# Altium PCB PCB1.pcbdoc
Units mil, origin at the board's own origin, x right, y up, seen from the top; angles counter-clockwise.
Board outline 3640 x 4230 mil, 2 copper layers (Top Layer, Bottom Layer); 68 components, 95 nets, 332 pads, 42 vias.
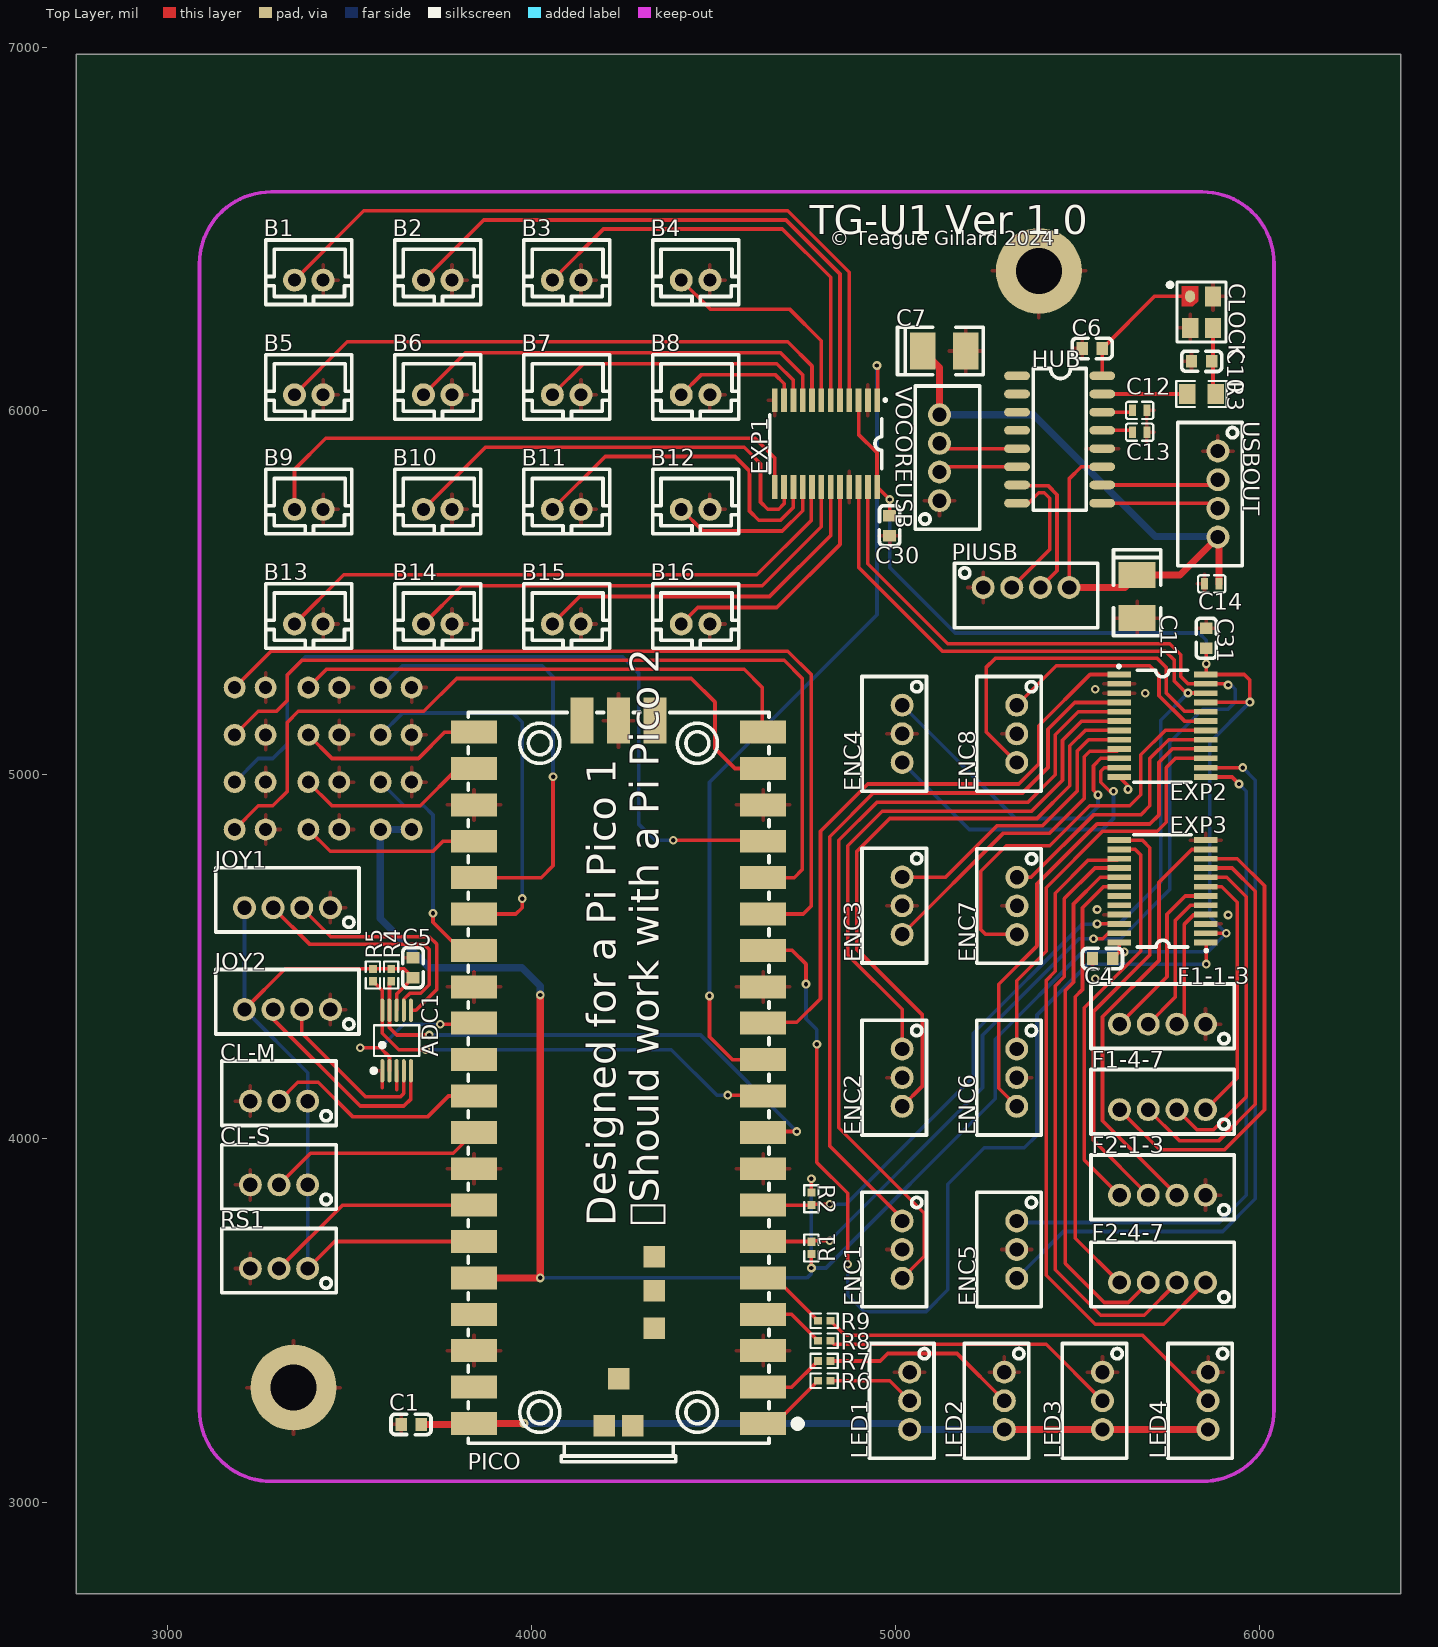
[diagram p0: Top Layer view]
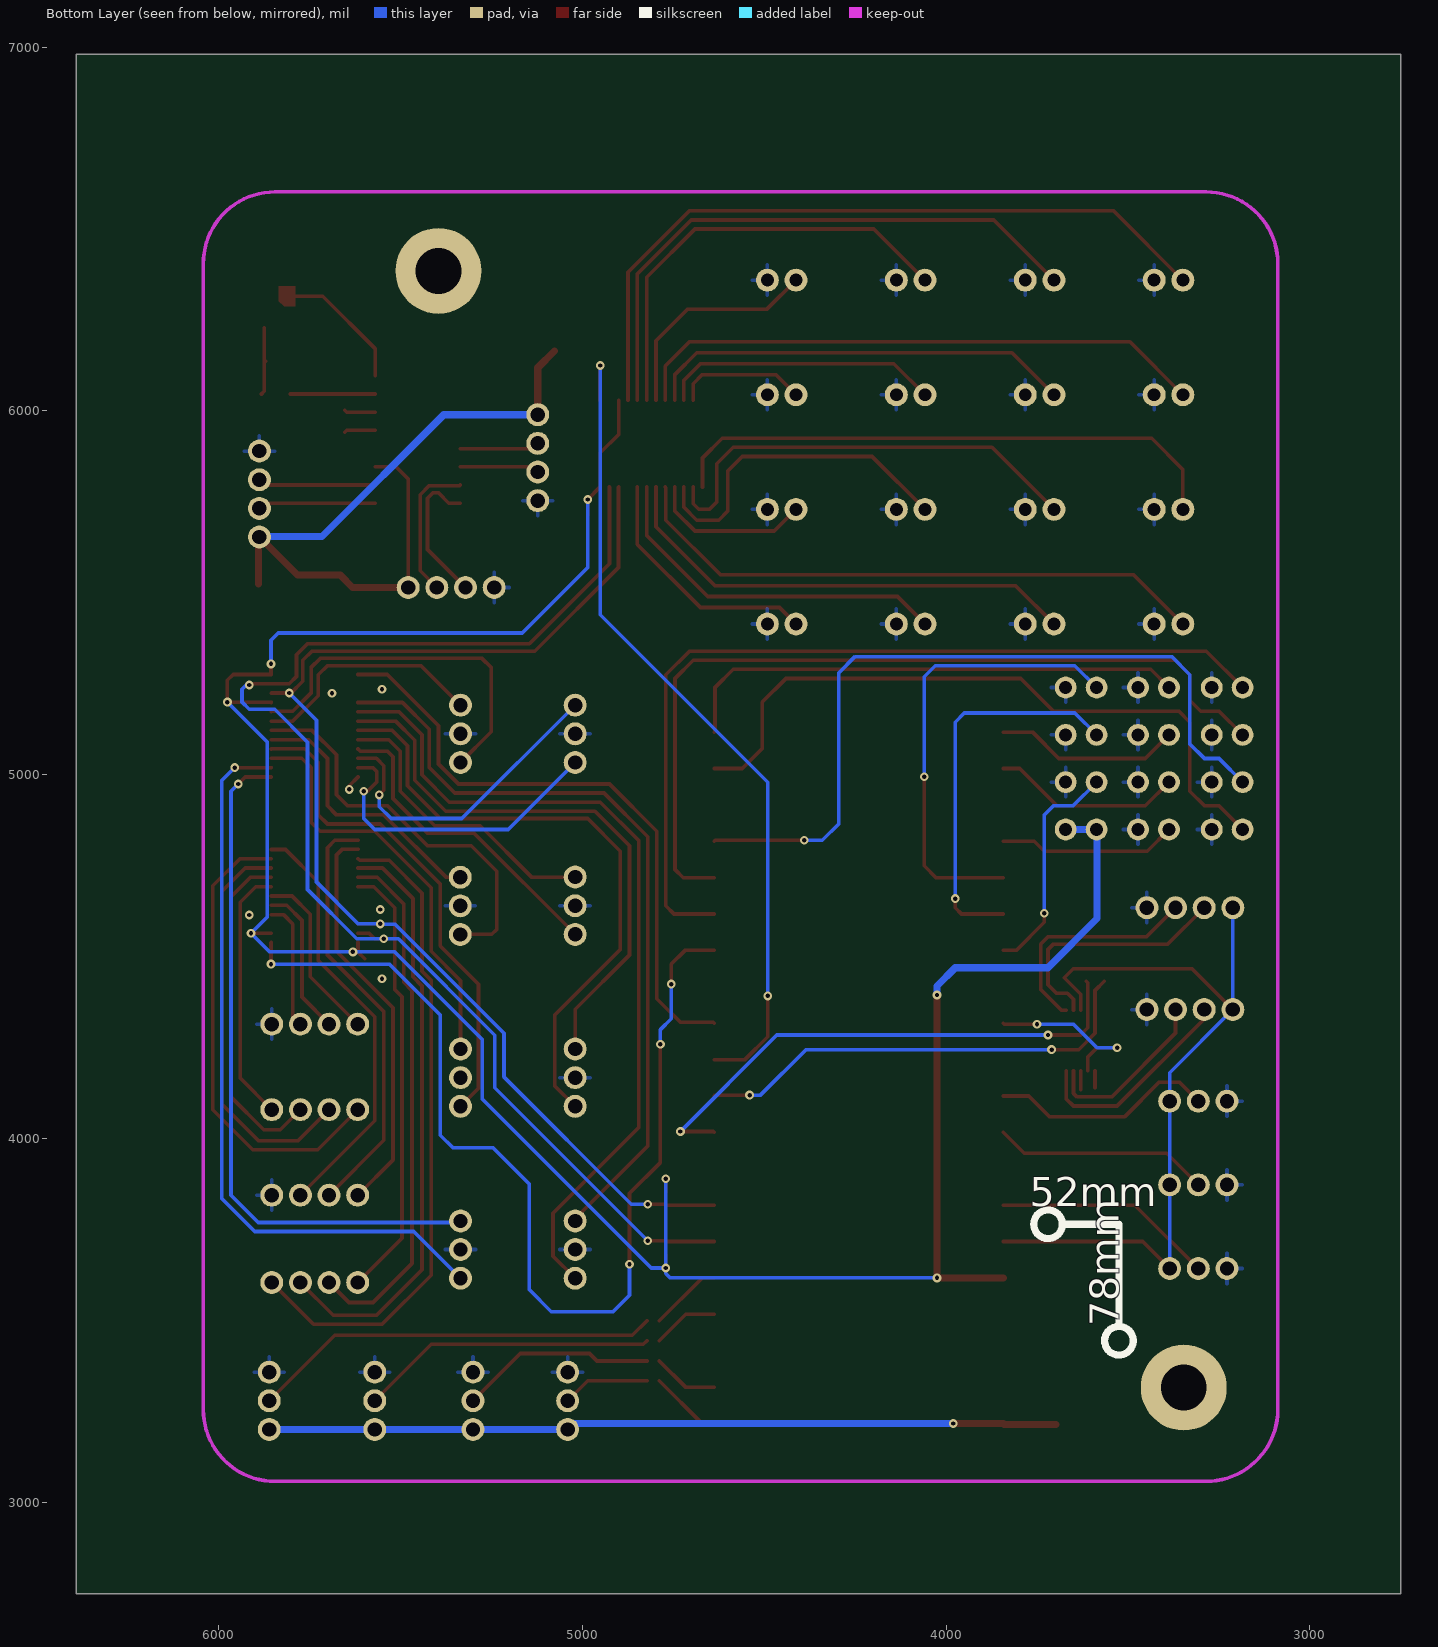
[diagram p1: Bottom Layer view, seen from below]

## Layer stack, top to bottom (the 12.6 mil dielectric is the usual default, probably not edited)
Top Layer: signal copper (thickness not stored)
Dielectric: dielectric 12.6, FR-4, Dk 4.8
Bottom Layer: signal copper (thickness not stored)

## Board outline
6390,2750 2750,2750 2750,6980 6390,6980

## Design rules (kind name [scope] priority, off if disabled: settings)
Clearance copperThickness1oz [All] p1: gap=7 ignorepadtopadclearanceinfootprint=FALSE except(4: Track-Track; 6: Track-SMDPad SMDPad-SMDPad Track-THPad SMDPad-THPad THPad-THPad Track-Via SMDPad-Via THPad-Via Via-Via SMDPad-Fill THPad-Fill Via-Fill Fill-Fill Track-Region SMDPad-Region THPad-Region Via-Region Region-Region Track-Poly SMDPad-Poly THPad-Poly Via-Poly Fill-Poly Region-Poly Poly-Poly Track-Text SMDPad-Text THPad-Text Via-Text Fill-Text Region-Text Poly-Text Text-Text; 6.9: Track-Hole SMDPad-Hole THPad-Hole Via-Hole Fill-Hole Region-Hole Poly-Hole Text-Hole Sheet-Hole; 11.8: Track-Fill Fill-Region Track-Sheet SMDPad-Sheet THPad-Sheet Via-Sheet Fill-Sheet Region-Sheet Poly-Sheet Text-Sheet)
Clearance copperThickness2oz [All] p1: gap=7 ignorepadtopadclearanceinfootprint=FALSE except(6: Track-SMDPad SMDPad-SMDPad Track-THPad SMDPad-THPad THPad-THPad Track-Via SMDPad-Via THPad-Via Via-Via SMDPad-Fill THPad-Fill Via-Fill Fill-Fill Track-Region SMDPad-Region THPad-Region Via-Region Region-Region Track-Poly SMDPad-Poly THPad-Poly Via-Poly Fill-Poly Region-Poly Poly-Poly Track-Text SMDPad-Text THPad-Text Via-Text Fill-Text Region-Text Poly-Text Text-Text; 6.9: Track-Hole SMDPad-Hole THPad-Hole Via-Hole Fill-Hole Region-Hole Poly-Hole Text-Hole Sheet-Hole; 8: Track-Track; 11.8: Track-Fill Fill-Region Track-Sheet SMDPad-Sheet THPad-Sheet Via-Sheet Fill-Sheet Region-Sheet Poly-Sheet Text-Sheet)
DiffPairsRouting differentialPair [All] p1: maxuncoupledlength=10 maxlimit=6 mostfreqgap=6 toplayer_minwidth=5 toplayer_prefwidth=10 toplayer_maxwidth=100 bottomlayer_minwidth=5 bottomlayer_prefwidth=10 bottomlayer_maxwidth=100
PasteMaskExpansion pasteMaskExpansion [All] p1:
PlaneConnect innerPlane [All] p1: planeconnectstyle=Relief reliefexpansion=20 reliefentries=4 reliefconductorwidth=10 reliefairgap=10
PolygonConnect copperRegion [All] p1: connectstyle=Relief reliefentries=4 reliefconductorwidth=10 polygonreliefangle="90 Angle" airgapwidth=10
RoutingVias viaSize [All] p1: viastyle="Through Hole" holewidth=12.0078 minholewidth=11.811 maxholewidth=248.0314 width=24.0158 minwidth=19.685 maxwidth=393.7008
SolderMaskExpansion solderMaskExpansion [All] p1: useseparateexpansions=TRUE expansion=2 expansionbottom=2
Width copperThickness1oz [All] p1: maxlimit=100 minlimit=5 preferedwidth=10
Width copperThickness2oz [All] p1: maxlimit=100 minlimit=8 preferedwidth=10

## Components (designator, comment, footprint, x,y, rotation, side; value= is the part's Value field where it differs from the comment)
ADC1 "ADS1115IDGSR" MSOP-10_L3.0-W3.0-P0.50-LS5.0-BL 3630,4270 r0 top
B1 "B2B-PH-K-S(LF)(SN)" CONN-TH_B2B-PH-K-S 3388.7,6359.53 r0 top
B2 "B2B-PH-K-S(LF)(SN)" CONN-TH_B2B-PH-K-S 3743.03,6359.53 r0 top
B3 "B2B-PH-K-S(LF)(SN)" CONN-TH_B2B-PH-K-S 4097.36,6359.53 r0 top
B4 "B2B-PH-K-S(LF)(SN)" CONN-TH_B2B-PH-K-S 4451.69,6359.53 r0 top
B5 "B2B-PH-K-S(LF)(SN)" CONN-TH_B2B-PH-K-S 3388.7,6044.57 r0 top
B6 "B2B-PH-K-S(LF)(SN)" CONN-TH_B2B-PH-K-S 3743.03,6044.57 r0 top
B7 "B2B-PH-K-S(LF)(SN)" CONN-TH_B2B-PH-K-S 4097.36,6044.57 r0 top
B8 "B2B-PH-K-S(LF)(SN)" CONN-TH_B2B-PH-K-S 4451.69,6044.57 r0 top
B9 "B2B-PH-K-S(LF)(SN)" CONN-TH_B2B-PH-K-S 3388.7,5729.61 r0 top
B10 "B2B-PH-K-S(LF)(SN)" CONN-TH_B2B-PH-K-S 3743.03,5729.61 r0 top
B11 "B2B-PH-K-S(LF)(SN)" CONN-TH_B2B-PH-K-S 4097.36,5729.61 r0 top
B12 "B2B-PH-K-S(LF)(SN)" CONN-TH_B2B-PH-K-S 4451.69,5729.61 r0 top
B13 "B2B-PH-K-S(LF)(SN)" CONN-TH_B2B-PH-K-S 3388.7,5414.65 r0 top
B14 "B2B-PH-K-S(LF)(SN)" CONN-TH_B2B-PH-K-S 3743.03,5414.65 r0 top
B15 "B2B-PH-K-S(LF)(SN)" CONN-TH_B2B-PH-K-S 4097.36,5414.65 r0 top
B16 "B2B-PH-K-S(LF)(SN)" CONN-TH_B2B-PH-K-S 4451.69,5414.65 r0 top
C1 "100n" C0603 3670,3215 r0 top
C4 "100nF" C0603 5570,4495 r0 top
C5 "100nF" C0603 3675,4470 r270 top
C6 "30pF" C0603 5542.03,6171.68 r0 top
C7 "100uF" CAP-SMD_L3.5-W2.8 5135,6165 r0 top
C10 "30pF" C0603 5842.03,6136.68 r180 top
C11 "100uF" CAP-SMD_L3.5-W2.8 5665,5490 r270 top
C12 "10uF" C0402 5672.03,6001.68 r0 top
C13 "10uF" C0402 5672.03,5941.68 r0 top
C14 "10uF" C0402 5870,5525 r180 top
C30 "100nF" C0603 4985,5685 r90 top
C31 "100nF" C0603 5855,5375 r270 top
CL-M "B3B-PH-K-S(LF)(SN)" CONN-TH_B3B-PH-K-S 3306.88,4103.35 r0 top
CL-S "B3B-PH-K-S(LF)(SN)" CONN-TH_B3B-PH-K-S 3306.88,3873.34 r0 top
CLOCK "12MHz" OSC-SMD_4P-L3.2-W2.5-BL 5842.03,6271.68 r270 top
ENC1 "B3B-PH-K-S(LF)(SN)" CONN-TH_B3B-PH-K-S 5019.3,3695.51 r90 top
ENC2 "B3B-PH-K-S(LF)(SN)" CONN-TH_B3B-PH-K-S 5019.3,4167.95 r90 top
ENC3 "B3B-PH-K-S(LF)(SN)" CONN-TH_B3B-PH-K-S 5019.3,4640.4 r90 top
ENC4 "B3B-PH-K-S(LF)(SN)" CONN-TH_B3B-PH-K-S 5019.3,5112.84 r90 top
ENC5 "B3B-PH-K-S(LF)(SN)" CONN-TH_B3B-PH-K-S 5334.26,3695.51 r90 top
ENC6 "B3B-PH-K-S(LF)(SN)" CONN-TH_B3B-PH-K-S 5334.26,4167.95 r90 top
ENC7 "B3B-PH-K-S(LF)(SN)" CONN-TH_B3B-PH-K-S 5335,4640 r90 top
ENC8 "B3B-PH-K-S(LF)(SN)" CONN-TH_B3B-PH-K-S 5334.26,5112.84 r90 top
EXP1 "PCA9555PW,118" TSSOP-24_L7.8-W4.4-P0.65-LS6.4-BL 4810,5910 r180 top
EXP2 "PCA9555PW,118" TSSOP-24_L7.8-W4.4-P0.65-LS6.4-BL 5735,5135 r270 top
EXP3 "PCA9555PW,118" TSSOP-24_L7.8-W4.4-P0.65-LS6.4-BL 5735,4680 r90 top
F1-1-3 "B4B-PH-K-S(LF)(SN)" CONN-TH_B4B-PH-K-S 5735,4315 r0 top
F1-4-7 "B4B-PH-K-S(LF)(SN)" CONN-TH_B4B-PH-K-S 5735,4080 r0 top
F2-1-3 "B4B-PH-K-S(LF)(SN)" CONN-TH_B4B-PH-K-S 5735,3845 r0 top
F2-4-7 "B4B-PH-K-S(LF)(SN)" CONN-TH_B4B-PH-K-S 5735,3605 r0 top
HUB "SL2.1A" SOP-16_L10.0-W3.9-P1.27-LS6.0-BL 5452.03,5921.68 r270 top
JOY1 "B4B-PH-K-S(LF)(SN)" CONN-TH_B4B-PH-K-S 3330,4635 r0 top
JOY2 "B4B-PH-K-S(LF)(SN)" CONN-TH_B4B-PH-K-S 3330,4355 r0 top
LED1 "B3B-PH-K-S(LF)(SN)" CONN-TH_B3B-PH-K-S 5040,3280 r90 top
LED2 "B3B-PH-K-S(LF)(SN)" CONN-TH_B3B-PH-K-S 5300,3280 r90 top
LED3 "B3B-PH-K-S(LF)(SN)" CONN-TH_B3B-PH-K-S 5570,3280 r90 top
LED4 "B3B-PH-K-S(LF)(SN)" CONN-TH_B3B-PH-K-S 5860,3280 r90 top
PICO "PICO" COMM-SMD_L51.0-W21.0-P2.54_SC0916 4240,4180 r90 top
PIUSB "B4B-PH-K-S(LF)(SN)" CONN-TH_B4B-PH-K-S 5360,5515 r180 top
R1 "2.2kΩ" R0402 4770,3700 r90 top
R2 "2.2kΩ" R0402 4770,3835 r270 top
R3 "1kΩ" R0805 5842.03,6046.68 r0 top
R4 "2.2kΩ" R0402 3615,4450 r90 top
R5 "2.2kΩ" R0402 3565,4450 r90 top
R6 "300Ω" R0402 4805,3335 r0 top
R7 "300Ω" R0402 4805,3389.39 r0 top
R8 "300Ω" R0402 4805,3445 r0 top
R9 "300Ω" R0402 4805,3500 r0 top
RS1 "B3B-PH-K-S(LF)(SN)" CONN-TH_B3B-PH-K-S 3306.88,3643.34 r0 top
USBOUT "B4B-PH-K-S(LF)(SN)" CONN-TH_B4B-PH-K-S 5887.03,5771.68 r90 top
VOCOREUSB "B4B-PH-K-S(LF)(SN)" CONN-TH_B4B-PH-K-S 5122.03,5871.68 r270 top

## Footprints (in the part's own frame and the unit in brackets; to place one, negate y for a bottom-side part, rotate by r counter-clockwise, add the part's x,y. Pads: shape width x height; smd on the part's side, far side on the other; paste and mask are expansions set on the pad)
C0402 [mm]
  rect 0.5x0.8 smd: 1(-0.5,0) 2(0.5,0)
  silkscreen extent -0.95,-0.6 0.95,0.6
C0603 [mm]
  rect 0.8x0.9 smd: 1(-0.7,0) 2(0.7,0)
  silkscreen extent -1.41,-0.71 1.39,0.72
CAP-SMD_L3.5-W2.8 [mm]
  rect 1.8x2.6 smd: 1(-1.501,0) 2(1.501,0)
  silkscreen extent -3.26,-1.65 2.73,1.65
COMM-SMD_L51.0-W21.0-P2.54_SC0916 [mm]
  rect 1.6x3.2 smd: 1(-24.445,-10.087) 2(-21.905,-10.087) 3(-19.365,-10.087) 4(-16.825,-10.087) 5(-14.285,-10.087) 6(-11.745,-10.087) 7(-9.205,-10.087) 8(-6.665,-10.087) 9(-4.125,-10.087) 10(-1.585,-10.087) 11(0.955,-10.087) 12(3.495,-10.087) 13(6.035,-10.087) 14(8.575,-10.087) 15(11.115,-10.087) 16(13.655,-10.087) 17(16.195,-10.087) 18(18.735,-10.087) 19(21.275,-10.087) 20(23.815,-10.087) 21(23.815,10.087) 22(21.275,10.087) 23(18.735,10.087) 24(16.195,10.087) 25(13.655,10.087) 26(11.115,10.087) 27(8.575,10.087) 28(6.035,10.087) 29(3.495,10.087) 30(0.955,10.087) 31(-1.585,10.087) 32(-4.125,10.087) 33(-6.665,10.087) 34(-9.205,10.087) 35(-11.745,10.087) 36(-14.285,10.087) 37(-16.825,10.087) 38(-19.365,10.087) 39(-21.905,10.087) 40(-24.445,10.087)
  rect 3.2x1.6 smd: 41(24.615,-2.54) 42(24.615,0) 43(24.615,2.54)
  rect 1.5x1.5 smd: TP1(-21.315,0) TP2(-24.615,1) TP3(-24.615,-1) TP4(-17.815,-2.5) TP5(-15.188,-2.5) TP6(-12.815,-2.5)
  silkscreen extent -27.11,-12.75 25.18,10.5
CONN-TH_B2B-PH-K-S [mm]
  round 1.6 hole 0.9: 1(1,0) 2(-1,0)
  silkscreen extent -3,-1.7 3,2.8
CONN-TH_B3B-PH-K-S [mm]
  round 1.6 hole 1: 1(2,0) 2(0,0) 3(-2,0)
  silkscreen extent -4,-1.7 4,2.8
CONN-TH_B4B-PH-K-S [mm]
  round 1.6 hole 1: 1(3,0) 2(1,0) 3(-1,0) 4(-3,0)
  silkscreen extent -5,-1.7 5,2.8
MSOP-10_L3.0-W3.0-P0.50-LS5.0-BL [mm]
  oval 0.28x1.62 smd: 1(-1,-2.11) 2(-0.5,-2.11) 3(0,-2.11) 4(0.5,-2.11) 5(1,-2.11) 6(1,2.11) 7(0.5,2.11) 8(0,2.11) 9(-0.5,2.11) 10(-1,2.11)
  silkscreen extent -1.74,-2.26 1.58,1.07
OSC-SMD_4P-L3.2-W2.5-BL [mm]
  oval 0.84x0.69 smd: 1(-1.1,-0.8)
  rect 1.4x1.15 smd: 2(1.1,-0.8) 3(1.1,0.8) 4(-1.1,0.8)
  Top Layer region: -1.8,-0.225 -0.762,-0.225 -0.4,-0.604 -0.4,-1.375 -1.8,-1.375
  silkscreen extent -2.1,-2.35 2.1,1.7
R0402 [mm]
  rect 0.566x0.54 smd: 1(-0.433,0) 2(0.433,0)
  silkscreen extent -0.94,-0.5 0.94,0.5
R0805 [mm]
  rect 1.133x1.377 smd: 1(-1,0) 2(1,0)
  silkscreen extent -1.76,-0.92 1.76,0.92
SOP-16_L10.0-W3.9-P1.27-LS6.0-BL [mm]
  oval 0.6x1.8 smd: 1(-4.445,-2.972) 2(-3.175,-2.972) 3(-1.905,-2.972) 4(-0.635,-2.972) 5(0.635,-2.972) 6(1.905,-2.972) 7(3.175,-2.972) 8(4.445,-2.972) 9(4.445,2.972) 10(3.175,2.972) 11(1.905,2.972) 12(0.635,2.972) 13(-0.635,2.972) 14(-1.905,2.972) 15(-3.175,2.972) 16(-4.445,2.972)
  silkscreen extent -4.95,-1.85 4.95,1.85
TSSOP-24_L7.8-W4.4-P0.65-LS6.4-BL [mm]
  rect 0.4x1.65 smd: 1(-3.575,-3.023) 2(-2.925,-3.023) 3(-2.275,-3.023) 4(-1.625,-3.023) 5(-0.975,-3.023) 6(-0.325,-3.023) 7(0.325,-3.023) 8(0.975,-3.023) 9(1.625,-3.023) 10(2.275,-3.023) 11(2.925,-3.023) 12(3.575,-3.023) 13(3.575,3.023) 14(2.925,3.023) 15(2.275,3.023) 16(1.625,3.023) 17(0.975,3.023) 18(0.325,3.023) 19(-0.325,3.023) 20(-0.975,3.023) 21(-1.625,3.023) 22(-2.275,3.023) 23(-2.925,3.023) 24(-3.575,3.023)
  silkscreen extent -4.24,-3.15 3.94,2.01

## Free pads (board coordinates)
  round 60 hole 36: 1(3185,5240) 1(3270,5240) 1(3387.5,5240) 1(3472.5,5240) 1(3586.27,5240) 1(3671.27,5240) 2(3185,5110) 2(3270,5110) 2(3387.5,5110) 2(3472.5,5110) 2(3586.27,5110) 2(3671.27,5110) 3(3185,4980) 3(3270,4980) 3(3387.5,4980) 3(3472.5,4980) 3(3586.27,4980) 3(3671.27,4980) 4(3185,4850) 4(3270,4850) 4(3387.5,4850) 4(3472.5,4850) 4(3586.27,4850) 4(3671.27,4850)
  round 236.22 hole 125.98: 1(3346.87,3316.21) 1(5395,6385)

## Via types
v1: diameter 24.02, hole 12.01, Top Layer to Bottom Layer, 42 vias

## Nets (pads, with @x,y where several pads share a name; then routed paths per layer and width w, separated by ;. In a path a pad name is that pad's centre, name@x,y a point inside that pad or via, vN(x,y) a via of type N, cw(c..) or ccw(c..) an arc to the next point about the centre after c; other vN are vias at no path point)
$C6_2: C6.2 CLOCK.1 HUB.16 | length 375.5
  Top Layer w10: HUB.16 5569.03,6171.12 C6.2 5712.9,6314.99 CLOCK.1
$C10_1: C10.1 CLOCK.3 R3.2 | length 190.5
  Top Layer w10: C10.1 C10.1@5873.53,6140.62 ; CLOCK.3 C10.1@5873.53,6140.62 ; R3.2 5873.53,6054.55 C10.1@5873.53,6140.62
$C12_1: C12.1 HUB.14 | length 85.4
  Top Layer w10: HUB.14 5647.35,5996.68 C12.1
$C13_1: C13.1 HUB.13 | length 85.4
  Top Layer w10: HUB.13 5647.35,5946.68 C13.1
$HUB1_5: HUB.5 VOCOREUSB.3 | length 219
  Top Layer w10: VOCOREUSB.3 5136.4,5896.68 HUB.5
$HUB1_6: HUB.6 VOCOREUSB.2 | length 219
  Top Layer w10: VOCOREUSB.2 5136.4,5846.68 HUB.6
$HUB1_7: HUB.7 PIUSB.3 | length 394.9
  Top Layer w10: HUB.7 5336.71,5795 5420,5795 5445,5770 5445,5560.63 PIUSB.3
$HUB1_8: HUB.8 PIUSB.2 | length 396.1
  Top Layer w10: PIUSB.2 5425,5619.37 5425,5760 5410,5775 5395,5775 5366.68,5746.68 HUB.8
$HUB1_9: HUB.9 USBOUT.3 | length 324
  Top Layer w10: HUB.9 5872.66,5746.68 USBOUT.3
$HUB1_10: HUB.10 USBOUT.2 | length 324
  Top Layer w10: HUB.10 5872.66,5796.68 USBOUT.2
$HUB1_15: HUB.15 R3.1 | length 233.6
  Top Layer w10: HUB.15 R3.1
$LED1_2: LED1.2 R6.2 | length 240.7
  Top Layer w10: R6.2 4985,3335 LED1.2
$LED2_2: LED2.2 R7.2 | length 540.3
  Top Layer w10: R7.2 4959.4,3389.39 4980,3410 5170,3410 LED2.2
$LED3_2: LED3.2 R8.2 | length 816.3
  Top Layer w10: R8.2 4832.04,3435 5415,3435 LED3.2
$LED4_2: LED4.2 R9.2 | length 1129.1
  Top Layer w10: R9.2 4862.04,3460 5680,3460 LED4.2
+5V: C1.2 C7.1 C11.1 C14.1 HUB.11 LED1.3 LED2.3 LED3.3 LED4.3 PICO.40 PIUSB.4 USBOUT.4 VOCOREUSB.4 | length 4827.8
  Top Layer w10: PIUSB.4 5478.11,5813.11 5511.68,5846.68 HUB.11
  Top Layer w19.68: C1.2 3840.26,3215 PICO.40 v1(3980,3217.6) ; C7.1 5122.03,6118.87 VOCOREUSB.4 ; LED2.3 LED3.3 LED4.3 ; PIUSB.4 5630.9,5515 C11.1 5782.56,5549.1 USBOUT.4 5889.68,5650.92 C14.1
  Bottom Layer w19.68: v1(3980,3217.6) 5023.66,3217.6 LED1.3 LED2.3 LED3.3 LED4.3 ; VOCOREUSB.4 5380.21,5989.79 5715,5655 5885.6,5655 USBOUT.4
ADC-VREF: ADC1.8 C5.2 CL-M.1 CL-S.1 JOY1.4 JOY2.4 PICO.35 R4.2 R5.2 RS1.1 | length 2179.3
  Top Layer w10: JOY2.4 3323.93,4467.04 R5.2 R4.2 3650.4,4467.04 C5.2 3630,4397.44 ADC1.8 ; RS1.1 3459.88,3717.6 PICO.35
  Bottom Layer w10: JOY1.4 JOY2.4 3385.62,4181.27 CL-M.1 CL-S.1 RS1.1
B1: B1.2 EXP1.4 | length 2025.6
  Top Layer w10: B1.2 3539.8,6550 4705,6550 4873.97,6381.03 EXP1.4
B2: B2.2 EXP1.5 | length 1622.3
  Top Layer w10: B2.2 3869.13,6525 4700,6525 4848.38,6376.62 EXP1.5
B3: B3.2 EXP1.6 | length 1216.2
  Top Layer w10: B3.2 4198.46,6500 4690,6500 4822.79,6367.21 EXP1.6
B4: B4.2 EXP1.7 | length 617.7
  Top Layer w10: B4.2 4491.85,6280 4710,6280 4797.21,6192.79 EXP1.7
B5: B5.2 EXP1.8 | length 1604.5
  Top Layer w10: B5.2 3494.76,6190 4705,6190 4771.61,6123.39 EXP1.8
B6: B6.2 EXP1.9 | length 1185.4
  Top Layer w10: B6.2 3819.09,6160 4685,6160 4746.02,6098.98 EXP1.9
B7: B7.2 EXP1.10 | length 772.2
  Top Layer w10: B7.2 4143.43,6130 4675,6130 4720.43,6084.57 EXP1.10
B8: B8.2 EXP1.11 | length 362.1
  Top Layer w10: B8.2 4467.76,6100 4670,6100 4695,6075 4695,6029.16 EXP1.11
B9: B9.2 EXP1.13 | length 1567.4
  Top Layer w10: B9.2 3349.33,5839.33 3435,5925 4615,5925 4669.26,5870.74 EXP1.13
B10: B10.2 EXP1.14 | length 1246
  Top Layer w10: B10.2 3874.06,5900 4585,5900 4630,5855 4630,5750 4650,5730 4680,5730 4694.84,5744.84 EXP1.14
B11: B11.2 EXP1.15 | length 929.8
  Top Layer w10: B11.2 4203.39,5875 4560,5875 4600,5835 4600,5725 4625,5700 4685,5700 4720.43,5735.43 EXP1.15
B12: B12.2 EXP1.16 | length 446.6
  Top Layer w10: B12.2 4471.93,5670 4690,5670 4746.02,5726.02 EXP1.16
B13: B13.2 EXP1.17 | length 1630.5
  Top Layer w10: B13.2 3484.69,5550 4620,5550 4770,5700 4770,5789.39 EXP1.17
B14: B14.2 EXP1.18 | length 1313.2
  Top Layer w10: B14.2 3809.02,5520 4635,5520 4797.21,5682.21 EXP1.18
B15: B15.2 EXP1.19 | length 998.7
  Top Layer w10: B15.2 4133.35,5490 4655,5490 4822.79,5657.79 EXP1.19
B16: B16.2 EXP1.20 | length 684.3
  Top Layer w10: B16.2 4457.68,5460 4675,5460 4848.38,5633.38 EXP1.20
CL-M: CL-M.2 PICO.31 | length 620.5
  Top Layer w10: CL-M.2 3358.54,4155 3415,4155 3509.92,4060.08 3715.08,4060.08 3772.6,4117.6 PICO.31
CL-S: CL-S.2 PICO.32 | length 595.7
  Top Layer w10: CL-S.2 3393.62,3960.08 3785.34,3960.08 PICO.32
ENC1-1: ENC1.1 EXP2.4 | length 2148.6
  Top Layer w10: ENC1.1 5019.3,3780.7 4820,3980 4820,4830 4940,4950 5350,4950 5420,5020 5420,5125 5493.97,5198.97 EXP2.4
ENC1-2: ENC1.3 EXP2.5 | length 2307.5
  Top Layer w10: ENC1.3 5080,3677.48 5080,3795 4845,4030 4845,4820 4950,4925 5365,4925 5440,5000 5440,5110 5503.38,5173.38 EXP2.5
ENC2-1: ENC2.1 EXP2.6 | length 1572.6
  Top Layer w10: ENC2.1 5019.3,4355.7 4870,4505 4870,4805 4965,4900 5375,4900 5460,4985 5460,5095 5512.79,5147.79 EXP2.6
ENC2-2: ENC2.3 EXP2.7 | length 1721.5
  Top Layer w10: ENC2.3 5075,4144.92 5075,4340 4895,4520 4895,4790 4985,4880 5390,4880 5480,4970 5480,5080 5522.21,5122.21 EXP2.7
ENC3-1: ENC3.1 EXP2.8 | length 817.5
  Top Layer w10: ENC3.1 5139.14,4719.14 5280,4860 5405,4860 5500,4955 5500,5065 5531.61,5096.61 EXP2.8
ENC3-2: ENC3.3 EXP2.9 | length 875.1
  Top Layer w10: ENC3.3 5297.64,4840 5425,4840 5520,4935 5520,5050 5535,5065 5609.98,5065 EXP2.9
ENC4-1: ENC4.1 EXP2.10 | length 877.9
  Top Layer w10: v1(5557.5,4945) 5545,4957.5 5545,5025 5565.43,5045.43 EXP2.10
  Bottom Layer w10: ENC4.1 5330.87,4880 5525,4880 5557.5,4912.5 v1(5557.5,4945)
ENC4-2: ENC4.3 EXP2.11 | length 874.8
  Top Layer w10: v1(5600,4955) 5590,4955 5565,4980 5565,5010 5574.84,5019.84 EXP2.11
  Bottom Layer w10: ENC4.3 5203.39,4850 5570,4850 5600,4880 v1(5600,4955)
ENC5-1: ENC5.1 EXP2.13 | length 1900.8
  Top Layer w10: EXP2.13 5925.74,4994.26 v1(5945,4975)
  Bottom Layer w10: ENC5.1 5338.51,3770 5890,3770 5965,3845 5965,4955 v1(5945,4975)
ENC5-2: ENC5.3 EXP2.14 | length 2046.7
  Top Layer w10: EXP2.14 5854.16,5020 v1(5955,5020)
  Bottom Layer w10: ENC5.3 5462.48,3745 5900,3745 5990,3835 5990,4985 v1(5955,5020)
ENC6-1: ENC6.1 EXP2.15 | length 1150.8
  Top Layer w10: ENC6.1 5334.26,4434.26 5415,4515 5415,4690 5570,4845 5720,4845 5745,4870 5745,5020 5770.43,5045.43 EXP2.15
ENC6-2: ENC6.3 EXP2.16 | length 1378.2
  Top Layer w10: ENC6.3 5285,4138.47 5285,4425 5390,4530 5390,4700 5555,4865 5700,4865 5725,4890 5725,5035 5762.07,5072.07 5852.95,5072.07 EXP2.16
ENC7-1: ENC7.1 EXP2.17 | length 752.2
  Top Layer w10: ENC7.1@5334.26,4719.14 5374.14,4719.14 5545,4890 5675,4890 5700,4915 5700,5045 5751.61,5096.61 EXP2.17
ENC7-2: ENC7.3 EXP2.18 | length 1108.6
  Top Layer w10: ENC7.3@5334.26,4561.66 5248.34,4561.66 5235,4575 5235,4735 5305,4805 5425,4805 5535,4915 5645,4915 5675,4945 5675,5055 5742.21,5122.21 EXP2.18
ENC8-1: ENC8.1 EXP2.19 | length 661.2
  Top Layer w10: ENC8.1 5442.68,5300 5700,5300 5725,5275 5725,5217.79 5795,5147.79 EXP2.19
ENC8-2: ENC8.3 EXP2.20 | length 1011.9
  Top Layer w10: ENC8.3 5250,5118.35 5250,5295 5275,5320 5720,5320 5745,5295 5745,5225 5795,5175 5852.38,5175 EXP2.20
EXP1: EXP1.1 PICO.11 | length 2305.9
  Top Layer w10: v1(4490,4392.6) 4490,4280 4552.4,4217.6 PICO.11 ; v1(4950,6125) 4952.07,6122.93 4952.07,6030.33 EXP1.1
  Bottom Layer w10: v1(4490,4392.6) 4490,4980 4950,5440 v1(4950,6125)
EXP2: EXP2.1 PICO.12 | length 1706.7
  Top Layer w10: PICO.12 4639.54,4320 4730,4320 4795,4385 4795,4845 4925,4975 5340,4975 5395,5030 5395,5135 5535.74,5275.74 EXP2.1
EXP3: EXP3.1 PICO.14 | length 2913.1
  Top Layer w10: PICO.14 4717.4,4517.6 4755,4480 v1(4755,4425) ; v1(4785,4260) 4785,3935 4870,3850 v1(4870,3655) ; EXP3.1 5855,4538.26 v1(5855,4480)
  Bottom Layer w10: v1(4755,4425) 4755,4330 4785,4300 v1(4785,4260) ; v1(4870,3655) 4870,3570 4915,3525 5085,3525 5145,3585 5145,3875 5245,3975 5355,3975 5390,4010 5390,4340 5530,4480 v1(5855,4480)
EXP4: ADC1.2 PICO.29 | length 469.4
  Top Layer w10: v1(3530,4250) 3585,4250 3610.32,4224.68 ADC1.2 ; v1(3750,4315) 3840.26,4315 PICO.29
  Bottom Layer w10: v1(3530,4250) 3585,4250 3650,4315 v1(3750,4315)
F1-1: EXP3.4 F1-1-3.2 | length 353.3
  Top Layer w10: F1-1-3.2 5795,4335.63 5795,4590 5821.03,4616.03 EXP3.4
F1-2: EXP3.5 F1-1-3.3 | length 417
  Top Layer w10: F1-1-3.3 5770,4389.37 5770,4600 5811.62,4641.62 EXP3.5
F1-3: EXP3.6 F1-1-3.4 | length 483.7
  Top Layer w10: F1-1-3.4 5747.21,4445.32 5747.21,4617.21 5797.21,4667.21 EXP3.6
F1-4: EXP3.7 F1-4-7.1 | length 709.7
  Top Layer w10: F1-4-7.1 5940,4166.89 5940,4650 5897.21,4692.79 EXP3.7
F1-5: EXP3.8 F1-4-7.2 | length 933.8
  Top Layer w10: F1-4-7.2 5829.37,4025 5875,4025 5965,4115 5965,4665 5911.61,4718.39 EXP3.8
F1-6: EXP3.9 F1-4-7.3 | length 1118.5
  Top Layer w10: F1-4-7.3 5780.63,3995 5890,3995 5990,4095 5990,4680 5926.02,4743.98 EXP3.9
F1-7: EXP3.10 F1-4-7.4 | length 1296.1
  Top Layer w10: F1-4-7.4 5726.89,3970 5905,3970 6015,4080 6015,4695 5940.43,4769.57 EXP3.10
F2-1: EXP3.11 F2-1-3.2 | length 1175.2
  Top Layer w10: F2-1-3.2 5570,4049.37 5570,4335 5725,4490 5725,4705 5815,4795 5853.84,4795 EXP3.11
F2-2: EXP3.13 F2-1-3.3 | length 1174.2
  Top Layer w10: EXP3.13 5616.74,4820 5680,4820 5700,4800 5700,4505 5545,4350 5545,3995.63 F2-1-3.3
F2-3: EXP3.14 F2-1-3.4 | length 1104.6
  Top Layer w10: EXP3.14 5659.84,4795.16 5675,4780 5675,4515 5520,4360 5520,3941.89 F2-1-3.4
F2-4: EXP3.15 F2-4-7.1 | length 1817.2
  Top Layer w10: EXP3.15 5611.43,4765 5530,4765 5440,4675 5440,4460 5415,4435 5415,3625 5550,3490 5738.11,3490 F2-4-7.1
F2-5: EXP3.16 F2-4-7.2 | length 1639.6
  Top Layer w10: EXP3.16 5548.98,4743.98 5465,4660 5465,4445 5440,4420 5440,3640 5565,3515 5684.37,3515 F2-4-7.2
F2-6: EXP3.17 F2-4-7.3 | length 1448.7
  Top Layer w10: EXP3.17 5563.39,4718.39 5490,4645 5490,4430 5467.5,4407.5 5467.5,3657.5 5575,3550 5640.63,3550 F2-4-7.3
F2-7: EXP3.18 F2-4-7.4 | length 1213.7
  Top Layer w10: EXP3.18 5572.79,4692.79 5515,4635 5515,4410 5495,4390 5495,3726.89 F2-4-7.4
GND: ADC1.1 ADC1.3 B1.1 B2.1 B3.1 B4.1 B5.1 B6.1 B7.1 B8.1 B9.1 B10.1 B11.1 B12.1 B13.1 B14.1 B15.1 B16.1 C1.1 C4.1 C5.1 C6.1 C7.2 C10.2 C11.2 C12.2 C13.2 C14.2 C30.1 C31.1 CL-M.3 CL-S.3 CLOCK.2 CLOCK.4 ENC1.2 ENC2.2 ENC3.2 ENC4.2 ENC5.2 ENC6.2 ENC7.2 ENC8.2 EXP1.2 EXP1.12 EXP1.21 EXP2.2 EXP2.3 EXP2.12 EXP3.3 EXP3.12 EXP3.21 F1-1-3.1 F2-1-3.1 HUB.12 JOY1.1 JOY2.1 LED1.1 LED2.1 LED3.1 LED4.1 pad.1@3270,5240 pad.1@3346.87,3316.21 pad.1@3472.5,5240 pad.1@3671.27,5240 pad.1@5395,6385 pad.2@3270,5110 pad.2@3472.5,5110 pad.2@3671.27,5110 pad.3@3270,4980 pad.3@3472.5,4980 pad.3@3671.27,4980 pad.4@3270,4850 pad.4@3472.5,4850 PICO.3 PICO.8 PICO.13 PICO.18 PICO.23 PICO.28 PICO.33 PICO.38 PICO.42 PIUSB.1 RS1.3 USBOUT.1 VOCOREUSB.1 | length 143.1
  Top Layer w10: 3590.63,4140 ADC1.1 ; 3630,4135 ADC1.3 ; EXP2.12 5640,4970.26 v1(5640,4960)
  other v1: 5550,4440 5915,4615 5555,4630 5687.33,5224.56 5550,5235
GP11: pad.1@3185,5240 PICO.15 | length 2430.5
  Top Layer w10: pad.1@3185,5240 3285,5340 4705,5340 4770,5275 4770,4640 4747.6,4617.6 PICO.15
GP12: pad.2@3185,5110 PICO.16 | length 2348.8
  Top Layer w10: pad.2@3185,5110 3250,5175 3300,5175 3330,5205 3330,5275 3370,5315 4695,5315 4745,5265 4745,4740 4722.6,4717.6 PICO.16
GP13: pad.3@3185,4980 PICO.17 | length 2159.6
  Top Layer w10: v1(4390,4820) 4634.74,4820 PICO.17
  Bottom Layer w10: pad.3@3185,4980 3250,5045 3290,5045 3330,5085 3330,5275 3380,5325 4250,5325 4295,5280 4295,4865 4340,4820 v1(4390,4820)
GP14: pad.4@3185,4850 PICO.19 | length 1912.4
  Top Layer w10: pad.4@3185,4850 3250,4915 3290,4915 3330,4955 3330,5145 3360,5175 3705,5175 3795,5265 4440,5265 4505,5200 4505,5072.6 4560,5017.6 PICO.19
GP15: pad.1@3387.5,5240 PICO.20 | length 1412.2
  Top Layer w10: pad.1@3387.5,5240 3437.5,5290 4585,5290 4635,5240 4635,5119.74 PICO.20
GP16: pad.2@3387.5,5110 PICO.21 | length 512.4
  Top Layer w10: pad.2@3387.5,5110 3452.5,5045 3690,5045 3762.6,5117.6 PICO.21
GP17: pad.3@3387.5,4980 PICO.22 | length 524.8
  Top Layer w10: pad.3@3387.5,4980 3452.5,4915 3695,4915 3797.6,5017.6 PICO.22
GP18: pad.4@3387.5,4850 PICO.24 | length 491.6
  Top Layer w10: pad.4@3387.5,4850 3447.5,4790 3730,4790 3757.6,4817.6 PICO.24
GP19: pad.1@3586.27,5240 PICO.25 | length 1261.6
  Top Layer w10: PICO.25 4027.6,4717.6 4060,4750 v1(4060,4995)
  Bottom Layer w10: pad.1@3586.27,5240 3646.27,5300 4030,5300 4060,5270 v1(4060,4995)
GP20: pad.2@3586.27,5110 PICO.26 | length 1073.3
  Top Layer w10: PICO.26 3957.6,4617.6 3975,4635 v1(3975,4660)
  Bottom Layer w10: pad.2@3586.27,5110 3646.27,5170 3950,5170 3975,5145 v1(3975,4660)
GP21: pad.3@3586.27,4980 PICO.27 | length 620.9
  Top Layer w10: v1(3730,4620) 3730,4595 3807.4,4517.6 PICO.27
  Bottom Layer w10: pad.3@3586.27,4980 3651.27,4915 3705,4915 3730,4890 v1(3730,4620)
JOY1-X: ADC1.4 JOY2.2 | length 483.7
  Top Layer w10: JOY2.2 3369.37,4290.63 3545,4115 3640,4115 3649.69,4124.69 ADC1.4
JOY1-Y: ADC1.5 JOY2.3 | length 589.1
  Top Layer w10: JOY2.3 3290.63,4329.37 3530,4090 3650,4090 3669.37,4109.37 ADC1.5
JOY2-X: ADC1.6 JOY1.2 | length 631.3
  Top Layer w10: JOY1.2 3449.37,4555 3720,4555 3740,4535 3740,4410 3683.07,4353.07 ADC1.6
JOY2-Y: ADC1.7 JOY1.3 | length 690.6
  Top Layer w10: JOY1.3 3390.63,4535 3705,4535 3720,4520 3720,4423.38 3696.62,4400 3666.59,4400 3649.69,4383.1 ADC1.7
LED1: PICO.1 R6.1 | length 199.4
  Top Layer w10: PICO.1 4670.56,3217.6 R6.1
LED2: PICO.2 R7.1 | length 180.6
  Top Layer w10: PICO.2 4716.16,3317.6 R7.1
LED3: PICO.4 R8.1 | length 180.9
  Top Layer w10: PICO.4 4715.36,3517.6 R8.1
LED4: PICO.5 R9.1 | length 199.5
  Top Layer w10: PICO.5 4670.36,3617.6 R9.1
RS1: PICO.34 RS1.2 | length 608.2
  Top Layer w10: RS1.2 3481.14,3817.6 PICO.34
SCL: EXP1.22 EXP2.22 EXP3.22 PICO.7 R2.2 | length 3494.5
  Top Layer w10: PICO.7 4769.64,3817.6 R2.2 4772.04,3820 v1(4820,3820) ; EXP1.22 4900,5790.56 4900,5570 5130,5340 5742.5,5340 5767.5,5315 5767.5,5257.5 5800,5225 v1(5805,5225) 5853.56,5225 EXP2.22 ; v1(5555,4590.44) EXP3.22
  Bottom Layer w10: v1(4820,3820) 4865,3820 5215,4170 5215,4290 5515,4590 5554.56,4590 v1(5555,4590.44) 5615,4590.44 5730,4705.44 5730,5150 v1(5805,5225)
SCL2: ADC1.10 PICO.10 R5.1 | length 1271.5
  Top Layer w10: R5.1 3590.63,4407.33 ADC1.10 3590.63,4290 3635.63,4245 v1(3710,4245) ; v1(4540,4120) 4634.74,4120 PICO.10
  Bottom Layer w10: v1(3710,4245) 4385,4245 4510,4120 v1(4540,4120)
SDA: EXP1.23 EXP2.23 EXP3.23 PICO.6 R1.2 | length 3745.7
  Top Layer w10: PICO.6 4769.44,3717.6 R1.2 4772.96,3720 v1(4820,3720) ; EXP1.23 4925,5790.85 4925,5580 5145,5360 5755,5360 5785,5330 5785,5270.15 5805,5250.15 EXP2.23 5911.92,5250.15 v1(5915,5247.07) ; v1(5545,4549.85) 5570.7,4549.85 5585.7,4564.85 EXP3.23
  Bottom Layer w10: v1(4820,3720) 5240,4140 5240,4284.85 5505,4549.85 v1(5545,4549.85) 5619.85,4549.85 5755,4685 5755,5090 5845,5180 5915,5180 5935,5200 5935,5235 5922.93,5247.07 v1(5915,5247.07)
SDA2: 
VCC: C4.2 C30.2 C31.2 EXP1.3 EXP1.24 EXP2.21 EXP2.24 EXP3.2 EXP3.24 pad.4@3586.27,4850 pad.4@3671.27,4850 PICO.36 R1.1 R2.1 | length 7292.7
  Top Layer w10: v1(4770,3645) R1.1 ; R2.1 v1(4770,3890) ; EXP1.3 4899.56,5935.44 4950,5885 4950,5791.74 EXP1.24 v1(4985,5756.74) C30.2 ; C4.2 5616,4513.44 ; EXP3.24 5616,4513.44 ; v1(5630,4513.44) 5616,4513.44 ; EXP3.2 v1(5910,4564.85) ; EXP2.21 5855.03,5200 v1(5975,5200) 5975,5260 5959.26,5275.74 EXP2.24 5855,5276.74 v1(5855,5305) C31.2
  Top Layer w19.68: PICO.36 v1(4025,3617.6) v1(4025,4395)
  Bottom Layer w10: v1(4025,3617.6) 4757.6,3617.6 4770,3630 v1(4770,3645) ; v1(4770,3890) v1(4770,3645) ; v1(4985,5756.74) 4985,5570 5165,5390 5835,5390 5855,5370 v1(5855,5305) ; v1(5975,5200) 5865,5090 5865,4609.85 v1(5910,4564.85) 5858.59,4513.44 v1(5630,4513.44) 5515,4513.44 5275,4273.44 5275,4110 4810,3645 v1(4770,3645)
  Bottom Layer w19.68: pad.4@3585,4850 3585,4605 3720,4470 3975,4470 4025,4420 v1(4025,4395) ; pad.4@3586.27,4850 pad.4@3671.27,4850
pads on no net: ADC1.9 EXP3.19 EXP3.20 HUB.1 HUB.2 HUB.3 HUB.4 PICO.9 PICO.30 PICO.37 PICO.39 PICO.41 PICO.43 PICO.TP1 PICO.TP2 PICO.TP3 PICO.TP4 PICO.TP5 PICO.TP6 R4.1
copper on no net: | length 1461.5
  Top Layer w10: 3615,4432.96 3610.32,4428.28 3610.32,4353.07 3610.32,4305 3630.32,4285 v1(3720,4285) ; 4637.14,4017.6 4639.54,4020 v1(4730,4020)
  Bottom Layer w10: v1(3720,4285) 4465,4285 v1(4730,4020)

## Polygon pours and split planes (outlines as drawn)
GND on Top Layer (solid, remove dead copper): 3000,3010 6115,3010 6115,6730 3000,6730
GND on Bottom Layer (solid, remove dead copper, pour order 2): 3025,3000 6140,3000 6140,6720 3025,6720

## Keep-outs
Board Outline Layer:
  lines w10: 3088.43,3255.59 ccw(c3285.28,3255.59) 3285.28,3058.74 5844.33,3058.74 ccw(c5844.33,3255.59) 6041.18,3255.59 6041.18,6405.2 ccw(c5844.33,6405.2) 5844.33,6602.05 3285.28,6602.05 ccw(c3285.28,6405.2) 3088.43,6405.2 3088.43,3255.59

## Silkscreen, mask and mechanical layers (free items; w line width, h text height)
Top Silkscreen Layer:
  text "TG-U1 Ver 1.0" at 4765,6485 h78.74
  text "© Teague Gillard 2024" at 4820,6455 h39.37
  text "Designed for a Pi Pico 1  /  Should work with a Pi Pico 2" at 4350,3760 h78.74 r90
Bottom Silkscreen Layer:
  circle w19.68: c3525,3445 r39.37
  circle w19.68: c3719.77,3765 r39.37
  lines w19.68: 3525,3484.03 3525,3765 3680.4,3765
  text "52mm" at 3770,3815 h78.74
  text "78mm" at 3525,3484.37 h78.74 r270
